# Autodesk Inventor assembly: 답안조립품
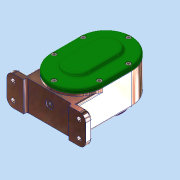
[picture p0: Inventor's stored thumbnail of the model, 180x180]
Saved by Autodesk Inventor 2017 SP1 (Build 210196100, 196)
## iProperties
Part Number: 답안조립품
Material: 일반
Document SubType Name: Assembly
Designer: MRC
Author: MRC
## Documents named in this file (19)
- C:\Users\MRC\Desktop\710609V1014\답안조립품.iam
- C:\Users\MRC\Desktop\710609V1014\본체.ipt
- C:\Users\MRC\Desktop\710609V1014\개스킷 A.ipt
- C:\Users\MRC\Desktop\710609V1014\개스킷 B.ipt
- C:\Users\MRC\Desktop\710609V1014\베어링 6001.ipt
- 베어링 6001.ipt
- C:\Users\MRC\Desktop\710609V1014\베어링 6002.ipt
- 베어링 6002.ipt
- C:\Users\MRC\Desktop\710609V1014\볼트 M4.ipt
- C:\Users\MRC\Desktop\710609V1014\스퍼기어 A.ipt
- C:\Users\MRC\Desktop\710609V1014\스퍼기어 B.ipt
- C:\Users\MRC\Desktop\710609V1014\오일 실 12 22 7.ipt
- C:\Users\MRC\Desktop\710609V1014\축 A.ipt
- C:\Users\MRC\Desktop\710609V1014\축 B.ipt
- C:\Users\MRC\Desktop\710609V1014\칼라.ipt
- C:\Users\MRC\Desktop\710609V1014\커버 A.ipt
- C:\Users\MRC\Desktop\710609V1014\커버 B.ipt
- C:\Users\MRC\Desktop\710609V1014\키 4 x 4 x 12.ipt
- C:\Users\MRC\Desktop\710609V1014\키 5 x 5 x 12.ipt
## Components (2 placed, 2 different names)
1. 개스킷 A:1
2. 개스킷 B:1
